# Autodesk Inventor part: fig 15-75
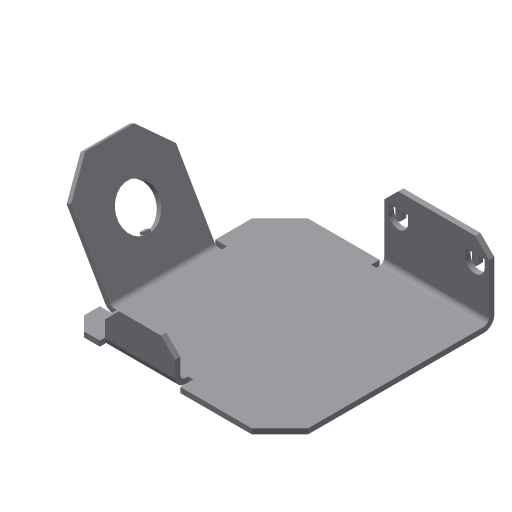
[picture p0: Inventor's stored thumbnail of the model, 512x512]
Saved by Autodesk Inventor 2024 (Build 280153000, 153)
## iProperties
Shininess: 77.0
Angle Display Precision: 2
Document Length Units: 11269
Document Angle Units: 11279
Document Time Units: 11290
Document Mass Units: 11283
Document Length Units Precision: 3
Document Angle Units Precision: 2
Created: 2002-04
Part Number: fig 15-75
Document SubType Name: Sheet Metal
Density: 1 g/cm^3
Sheet Metal Rule: Default
Material: Generic
Appearance: Default
Density: 0.0
Volumn: 0.0
Area: 0.0
PropertySet Name: Model Information
Control State: 0
Master: False
Checked Out: False
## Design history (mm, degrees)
node "Face1"
  sketch "Sketch1"
    geometry: L1 (12.647, 25.882)-(12.647, -14.118); L2 (12.647, -14.118)-(-17.353, -14.118); L3 (-17.353, -14.118)-(-17.353, 15.882); L4 (-17.353, 15.882)-(-2.353, 15.882); L5 (-2.353, 15.882)-(-2.353, 25.882); L6 (-2.353, 25.882)-(12.647, 25.882); 1 further point
    constraints: 12 end point, 4 parallel, 1 perpendicular
    dimensions: "d5" = 30 distance of L2.end L3.end; "d6" = 10 distance of L4.end L5.end; "d7" = 15 distance of L3.end L4.end; "d25" = 15 distance of L5.end L1.start
sketch "Sketch3"
  geometry: L1 (10, -15)-(10, 0)
  constraints: 2 end point
feature "Fold3" sketch "Sketch3" dims "d26" = 0.75 (= BendRadius), "d27" = 90 deg, "d28" = 0.75 (= BendRadius), "d96" = 0.75 (= BendReliefWidth), "d97" = 0.375 (= BendReliefDepth), "d98" = 1.5 (= MinimumRemnant), "d113" = 0.75 (= Thickness), "SeamGap" = 0.01
node "Flange2"
sketch "Sketch6"
  geometry: L1 (-6.914, 3.413)-(-5.843, 3.413); L2 (-5.843, 0.624)-(-6.914, 0.624); L3 (-6.914, 2.432)-(-5.843, 2.432); L4 (-5.843, 1.605)-(-6.914, 1.605); L5 (-6.914, 0.624)-(-6.914, 1.605); L6 (-6.914, 2.432)-(-6.914, 3.413); L7 (-6.914, 12.568)-(-6.914, 11.587); L8 (-6.914, 14.376)-(-6.914, 13.395); L9 (-6.914, 11.587)-(-5.843, 11.587); L10 (-5.843, 14.376)-(-6.914, 14.376); L11 (-6.914, 12.568)-(-5.843, 12.568); L12 (-5.843, 13.395)-(-6.914, 13.395); A1 r 1.394 centre (-5.843, 2.018) between (-5.843, 0.624) and (-5.843, 3.413); A2 r 0.413 centre (-5.843, 2.018) between (-5.843, 1.605) and (-5.843, 2.432); A3 r 1.394 centre (-5.843, 12.982) between (-5.843, 11.587) and (-5.843, 14.376); A4 r 0.413 centre (-5.843, 12.982) between (-5.843, 12.568) and (-5.843, 13.395)
  constraints: 24 end point, 8 point on circle, 4 centre point, 3 equal length, 1 perpendicular
cut "Cut1" sketch "Sketch6" dims "d49" = 0.75 (= Thickness), "d50" = 0
node "Flange3"
feature "Corner Chamfer1" dims "d70" = 4, "d71" = 4, angle "d105" = 45 deg
feature "Corner Chamfer2" dims "d72" = 2, "d73" = 2, angle "d106" = 45 deg
sketch "Sketch10"
  geometry: 1 further point
feature "iFeature15:3" sketch "Sketch10"
body "Solid1"
face "Plate1" dims "d113" = 0.75 (= Thickness)
sketch "Sketch5"
  geometry: L1 (20, 0)-(5, 0); L2 (5, 0)-(5, 15); L3 (5, 15)-(20, 15); L4 (20, 15)-(20, 0)
  constraints: 8 end point
face "Plate6" dims "d35" = 10, "d36" = 5, "d38" = 15, "d39" = 60 deg, "d40" = 0.75 (= BendRadius), "d113" = 0.75 (= Thickness), "MinimumRemnant" = 1.5 (= 2 x Thickness), "BendReliefWidth" = 0.75 (= Thickness)
bend "Bend5" dims "d38" = 15, "d39" = 60 deg, "d40" = 0.75 (= BendRadius), "d99" = 0.75 (= BendReliefWidth), "d100" = 0.375 (= BendReliefDepth), "d101" = 1.5 (= MinimumRemnant), "d113" = 0.75 (= Thickness), "SeamGap" = 0.01, "MinimumRemnant" = 1.5 (= 2 x Thickness), "BendReliefWidth" = 0.75 (= Thickness), "TransitionRadius" = 0.75 (= BendRadius)
sketch "Sketch7"
  geometry: L1 (25, 0)-(15, 0); L2 (15, 0)-(15, 5); L3 (15, 5)-(25, 5); L4 (25, 5)-(25, 0)
  constraints: 8 end point
face "Plate7" dims "d57" = 5, "d58" = 10, "d60" = 5, "d61" = 90 deg, "d62" = 0.75 (= BendRadius), "d113" = 0.75 (= Thickness), "MinimumRemnant" = 1.5 (= 2 x Thickness), "BendReliefWidth" = 0.75 (= Thickness)
bend "Bend7" dims "d59" = 0.75 (= BendRadius), "d60" = 5, "d61" = 90 deg, "d62" = 0.75 (= BendRadius), "d102" = 0.75 (= BendReliefWidth), "d103" = 0.375 (= BendReliefDepth), "d104" = 1.5 (= MinimumRemnant), "d113" = 0.75 (= Thickness), "SeamGap" = 0.01, "MinimumRemnant" = 1.5 (= 2 x Thickness), "BendReliefWidth" = 0.75 (= Thickness)
other parameters: "Thickness" = 0.75, "BendRadius" = 0.75 (= Thickness), "BendReliefDepth" = 0.375 (= 0.5 x Thickness), "CornerReliefSize" = 3 (= 4 x Thickness), "d0" = 0.75 (= BendRadius), "d13" = 0.75 (= BendRadius), "d31" = 0.75 (= BendRadius), "d37" = 0.75 (= BendRadius), "d112" = 0, "JacobiRadiusSize" = 0.75 (= Thickness), "GapSize" = 0.75 (= Thickness)
